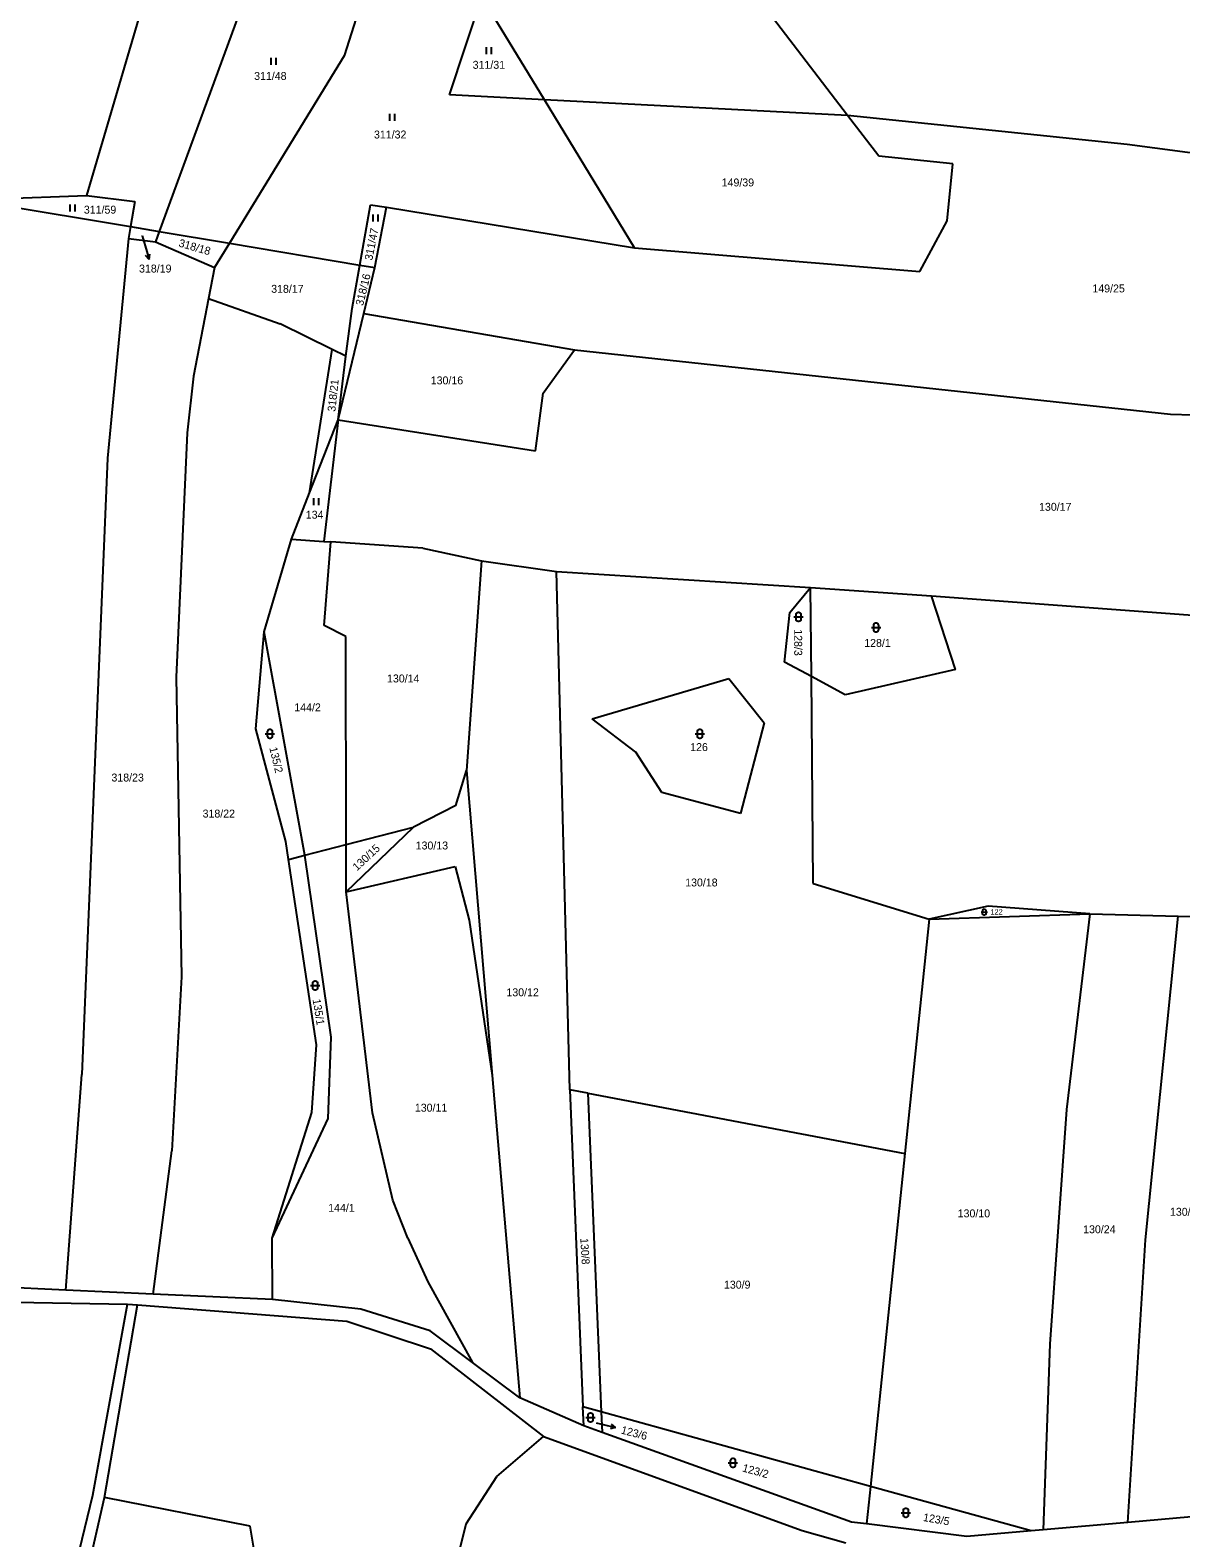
# Model space of a CAD drawing. Extents: x -791032 to -787751, y -1106872 to -1104403.
# Drawn here: x -789932.2 to -789685.4, y -1105545 to -1105221.6 of the extents above; entities that cross this region are included whole.
import ezdxf

# ---------------------------------------------------------------- set-up
doc = ezdxf.new("R2010")
doc.units = 0
for name, color, linetype in [('Komunikace', 7, 'Continuous'), ('Vrstva 1', 7, 'Continuous'), ('Vrstva 14', 7, 'Continuous'), ('Vrstva 16', 7, 'Continuous'), ('Vrstva 23', 7, 'Continuous')]:
    doc.layers.add(name, color=color, linetype=linetype)

msp = doc.modelspace()

# ---------------------------------------------------------------- linework, layer by layer
at = {"layer": 'Komunikace'}
for p, q in [((-789908.19, -1105265.74), (-789907.55, -1105267.91)), ((-789810.78, -1105520.32), (-789809.56, -1105520.63))]:
    msp.add_line(p, q, dxfattribs=at)
at = {"layer": 'Vrstva 1'}
for p, q in [((-789898.9, -1105184.93), (-789920.1, -1105257.09)), ((-789876.8, -1105189.18), (-789904.53, -1105264.78)), ((-789854.85, -1105195.52), (-789864.85, -1105227.14)), ((-789756.88, -1105239.91), (-789778.37, -1105211.87)), ((-789842.27, -1105235.52), (-789835.33, -1105214.49)), ((-789821.88, -1105236.57), (-789835.33, -1105214.49)), ((-789864.85, -1105227.14), (-789889.45, -1105267.31)), ((-789821.88, -1105236.57), (-789842.27, -1105235.52)), ((-789756.88, -1105239.91), (-789821.88, -1105236.57)), ((-789802.56, -1105268.3), (-789821.88, -1105236.57)), ((-789696.9, -1105246.15), (-789756.88, -1105239.91)), ((-789750.21, -1105248.61), (-789756.88, -1105239.91)), ((-789618.05, -1105256.49), (-789696.9, -1105246.15)), ((-789734.32, -1105250.31), (-789750.21, -1105248.61)), ((-789735.55, -1105262.51), (-789734.32, -1105250.31)), ((-789945.15, -1105257.97), (-789920.1, -1105257.09)), ((-789945.15, -1105257.97), (-789910.66, -1105263.75)), ((-789920.1, -1105257.09), (-789909.78, -1105258.37)), ((-789909.78, -1105258.37), (-789910.66, -1105263.75)), ((-789861.5, -1105272), (-789859.18, -1105259.05)), ((-789859.18, -1105259.05), (-789855.77, -1105259.61)), ((-789858.3, -1105272.54), (-789855.77, -1105259.61)), ((-789855.77, -1105259.61), (-789802.56, -1105268.3)), ((-789741.41, -1105273.39), (-789735.55, -1105262.51)), ((-789910.66, -1105263.75), (-789911.08, -1105266.33)), ((-789910.66, -1105263.75), (-789904.53, -1105264.78)), ((-789904.53, -1105264.78), (-789905.34, -1105267)), ((-789904.53, -1105264.78), (-789889.45, -1105267.31)), ((-789911.08, -1105266.33), (-789915.61, -1105313.42)), ((-789911.08, -1105266.33), (-789905.34, -1105267)), ((-789905.34, -1105267), (-789892.65, -1105272.54)), ((-789889.45, -1105267.31), (-789892.65, -1105272.54)), ((-789889.45, -1105267.31), (-789861.5, -1105272)), ((-789802.56, -1105268.3), (-789741.41, -1105273.39)), ((-789863.17, -1105281.31), (-789861.5, -1105272)), ((-789861.5, -1105272), (-789858.3, -1105272.54)), ((-789892.65, -1105272.54), (-789893.94, -1105279.16)), ((-789860.67, -1105282.39), (-789858.3, -1105272.54)), ((-789893.94, -1105279.16), (-789897.2, -1105295.83)), ((-789893.94, -1105279.16), (-789878.56, -1105284.6)), ((-789864.46, -1105291.57), (-789863.17, -1105281.31)), ((-789867.4, -1105290.11), (-789878.56, -1105284.6)), ((-789866.17, -1105305.19), (-789860.67, -1105282.39)), ((-789860.67, -1105282.39), (-789815.45, -1105290.19)), ((-789872.27, -1105320.87), (-789867.4, -1105290.11)), ((-789864.46, -1105291.57), (-789867.4, -1105290.11)), ((-789866.17, -1105305.19), (-789864.46, -1105291.57)), ((-789822.2, -1105299.47), (-789815.45, -1105290.19)), ((-789815.45, -1105290.19), (-789687.61, -1105303.97)), ((-789897.2, -1105295.83), (-789898.51, -1105308.02)), ((-789823.79, -1105311.85), (-789822.2, -1105299.47)), ((-789687.61, -1105303.97), (-789663.28, -1105304.71)), ((-789898.51, -1105308.02), (-789900.89, -1105360.37)), ((-789872.27, -1105320.87), (-789866.17, -1105305.19)), ((-789866.17, -1105305.19), (-789869.21, -1105331.3)), ((-789866.17, -1105305.19), (-789823.79, -1105311.85)), ((-789915.61, -1105313.42), (-789921.14, -1105445.65)), ((-789876.15, -1105330.83), (-789872.27, -1105320.87)), ((-789882.03, -1105350.67), (-789876.15, -1105330.83)), ((-789876.15, -1105330.83), (-789869.21, -1105331.3)), ((-789869.21, -1105331.3), (-789867.7, -1105331.4)), ((-789869.11, -1105349.31), (-789867.7, -1105331.4)), ((-789848, -1105332.7), (-789867.7, -1105331.4)), ((-789848, -1105332.7), (-789835.42, -1105335.45)), ((-789835.42, -1105335.45), (-789838.65, -1105380.44)), ((-789835.42, -1105335.45), (-789819.35, -1105337.71)), ((-789819.35, -1105337.71), (-789764.83, -1105341.18)), ((-789816.49, -1105448.92), (-789819.35, -1105337.71)), ((-789769.27, -1105346.53), (-789764.83, -1105341.18)), ((-789764.83, -1105341.18), (-789738.92, -1105342.96)), ((-789764.66, -1105360.28), (-789764.83, -1105341.18)), ((-789733.72, -1105358.79), (-789738.92, -1105342.96)), ((-789738.92, -1105342.96), (-789559.95, -1105356.13)), ((-789770.44, -1105357.17), (-789769.27, -1105346.53)), ((-789864.52, -1105351.67), (-789869.11, -1105349.31)), ((-789883.79, -1105371.5), (-789882.03, -1105350.67)), ((-789873.29, -1105398.59), (-789882.03, -1105350.67)), ((-789864.42, -1105396.31), (-789864.52, -1105351.67)), ((-789764.66, -1105360.28), (-789770.44, -1105357.17)), ((-789733.72, -1105358.79), (-789757.4, -1105364.19)), ((-789900.89, -1105360.37), (-789899.74, -1105424.65)), ((-789811.7, -1105369.36), (-789782.32, -1105360.67)), ((-789782.32, -1105360.67), (-789774.8, -1105370.19)), ((-789757.4, -1105364.19), (-789764.66, -1105360.28)), ((-789764.25, -1105404.69), (-789764.66, -1105360.28)), ((-789802.29, -1105376.51), (-789811.7, -1105369.36)), ((-789877.39, -1105395.62), (-789883.79, -1105371.5)), ((-789774.8, -1105370.19), (-789779.84, -1105389.62)), ((-789796.71, -1105385.15), (-789802.29, -1105376.51)), ((-789840.88, -1105387.94), (-789838.65, -1105380.44)), ((-789838.65, -1105380.44), (-789833.09, -1105445.85)), ((-789779.84, -1105389.62), (-789796.71, -1105385.15)), ((-789840.88, -1105387.94), (-789850, -1105392.59)), ((-789864.42, -1105396.31), (-789850, -1105392.59)), ((-789864.4, -1105406.48), (-789850, -1105392.59)), ((-789876.81, -1105399.51), (-789877.39, -1105395.62)), ((-789876.81, -1105399.51), (-789873.29, -1105398.59)), ((-789873.29, -1105398.59), (-789864.42, -1105396.31)), ((-789867.63, -1105437.61), (-789873.29, -1105398.59)), ((-789864.4, -1105406.48), (-789864.42, -1105396.31)), ((-789870.82, -1105439.27), (-789876.81, -1105399.51)), ((-789864.4, -1105406.48), (-789841.03, -1105400.98)), ((-789841.03, -1105400.98), (-789838.03, -1105412.49)), ((-789764.25, -1105404.69), (-789739.37, -1105412.28)), ((-789858.75, -1105453.85), (-789864.4, -1105406.48)), ((-789726.73, -1105409.55), (-789739.37, -1105412.28)), ((-789739.37, -1105412.28), (-789704.93, -1105411.19)), ((-789704.93, -1105411.19), (-789726.73, -1105409.55)), ((-789704.93, -1105411.19), (-789709.91, -1105453.12)), ((-789704.93, -1105411.19), (-789686.01, -1105411.64)), ((-789838.03, -1105412.49), (-789833.09, -1105445.85)), ((-789739.37, -1105412.28), (-789744.59, -1105462.54)), ((-789693.02, -1105481.06), (-789686.01, -1105411.64)), ((-789686.01, -1105411.64), (-789667.88, -1105412.07)), ((-789899.74, -1105424.65), (-789901.79, -1105461.99)), ((-789871.82, -1105453.76), (-789870.82, -1105439.27)), ((-789868.28, -1105455.1), (-789867.63, -1105437.61)), ((-789924.58, -1105491.88), (-789921.14, -1105445.65)), ((-789833.09, -1105445.85), (-789827.21, -1105515)), ((-789812.58, -1105449.66), (-789816.49, -1105448.92)), ((-789816.49, -1105448.92), (-789813.64, -1105516.91)), ((-789812.58, -1105449.66), (-789744.59, -1105462.54)), ((-789812.58, -1105449.66), (-789809.7, -1105518)), ((-789709.91, -1105453.12), (-789713.54, -1105503.51)), ((-789880.28, -1105480.76), (-789871.82, -1105453.76)), ((-789880.28, -1105480.76), (-789868.28, -1105455.1)), ((-789854.4, -1105472.57), (-789858.75, -1105453.85)), ((-789905.81, -1105492.73), (-789901.79, -1105461.99)), ((-789744.59, -1105462.54), (-789752, -1105533.98)), ((-789851.22, -1105480.73), (-789854.4, -1105472.57)), ((-789880.25, -1105493.9), (-789880.28, -1105480.76)), ((-789851.22, -1105480.73), (-789846.93, -1105490.11)), ((-789696.75, -1105541.71), (-789693.02, -1105481.06)), ((-789924.58, -1105491.88), (-789962.46, -1105490.15)), ((-789905.81, -1105492.73), (-789924.58, -1105491.88)), ((-789846.93, -1105490.11), (-789837.3, -1105507.43)), ((-789968.63, -1105493.94), (-789911.33, -1105494.89)), ((-789918.75, -1105535.87), (-789911.33, -1105494.89)), ((-789916.23, -1105536.35), (-789909.16, -1105495.06)), ((-789911.33, -1105494.89), (-789909.16, -1105495.06)), ((-789909.16, -1105495.06), (-789864.3, -1105498.57)), ((-789880.25, -1105493.9), (-789905.81, -1105492.73)), ((-789861.27, -1105495.99), (-789880.25, -1105493.9)), ((-789864.3, -1105498.57), (-789846.35, -1105504.45)), ((-789846.42, -1105500.6), (-789861.27, -1105495.99)), ((-789837.3, -1105507.43), (-789846.42, -1105500.6)), ((-789846.35, -1105504.45), (-789822.11, -1105523.27)), ((-789713.54, -1105503.51), (-789714.97, -1105543.3)), ((-789827.21, -1105515), (-789837.3, -1105507.43)), ((-789813.47, -1105520.96), (-789827.21, -1105515)), ((-789809.7, -1105518), (-789813.64, -1105516.91)), ((-789813.47, -1105520.96), (-789813.64, -1105516.91)), ((-789752, -1105533.98), (-789809.7, -1105518)), ((-789809.7, -1105518), (-789809.51, -1105522.39)), ((-789809.51, -1105522.39), (-789813.47, -1105520.96)), ((-789832.11, -1105531.85), (-789822.11, -1105523.27)), ((-789822.11, -1105523.27), (-789766.64, -1105543.45)), ((-789756.02, -1105541.64), (-789809.51, -1105522.39)), ((-789838.71, -1105542.04), (-789832.11, -1105531.85)), ((-789752, -1105533.98), (-789752.84, -1105542.04)), ((-789717.55, -1105543.53), (-789752, -1105533.98)), ((-789930, -1105581.73), (-789918.75, -1105535.87)), ((-789926.61, -1105581.71), (-789916.23, -1105536.35)), ((-789884.98, -1105542.5), (-789916.23, -1105536.35)), ((-789679.89, -1105540.23), (-789696.75, -1105541.71)), ((-789882.2, -1105559.31), (-789884.98, -1105542.5)), ((-789841.82, -1105554.77), (-789838.71, -1105542.04)), ((-789766.64, -1105543.45), (-789757.27, -1105546.07)), ((-789752.84, -1105542.04), (-789756.02, -1105541.64)), ((-789731.29, -1105544.73), (-789752.84, -1105542.04)), ((-789717.55, -1105543.53), (-789731.29, -1105544.73)), ((-789714.97, -1105543.3), (-789717.55, -1105543.53)), ((-789696.75, -1105541.71), (-789714.97, -1105543.3))]:
    msp.add_line(p, q, dxfattribs=at)
at = {"layer": 'Vrstva 16'}
for p, q in [((-789907.55, -1105267.91), (-789906.701, -1105270.787)), ((-789906.701, -1105270.787), (-789907.463, -1105269.969)), ((-789906.701, -1105270.787), (-789906.504, -1105269.686)), ((-789809.56, -1105520.63), (-789806.65, -1105521.362)), ((-789806.65, -1105521.362), (-789807.742, -1105521.603)), ((-789806.65, -1105521.362), (-789807.498, -1105520.633))]:
    msp.add_line(p, q, dxfattribs=at)
at = {"layer": 'Vrstva 23'}
for p, q in [((-789834.31, -1105226.78), (-789834.31, -1105225.28)), ((-789833.31, -1105225.28), (-789833.31, -1105226.78)), ((-789880.54, -1105229.04), (-789880.54, -1105227.54)), ((-789879.54, -1105227.54), (-789879.54, -1105229.04)), ((-789855.07, -1105241.07), (-789855.07, -1105239.57)), ((-789854.07, -1105239.57), (-789854.07, -1105241.07)), ((-789923.61, -1105260.51), (-789923.61, -1105259.01)), ((-789922.61, -1105259.01), (-789922.61, -1105260.51)), ((-789858.62, -1105262.63), (-789858.62, -1105261.13)), ((-789857.62, -1105261.13), (-789857.62, -1105262.63)), ((-789871.34, -1105323.5), (-789871.34, -1105322)), ((-789870.34, -1105322), (-789870.34, -1105323.5)), ((-789767.91, -1105346.89), (-789767.81, -1105346.69)), ((-789767.81, -1105346.69), (-789767.71, -1105346.59)), ((-789767.71, -1105346.59), (-789767.51, -1105346.49)), ((-789767.51, -1105346.49), (-789767.31, -1105346.49)), ((-789767.31, -1105346.49), (-789767.11, -1105346.59)), ((-789767.11, -1105346.59), (-789767.01, -1105346.69)), ((-789767.01, -1105346.69), (-789766.91, -1105346.89)), ((-789768.41, -1105347.49), (-789766.41, -1105347.49)), ((-789767.91, -1105348.09), (-789767.91, -1105346.89)), ((-789767.81, -1105348.29), (-789767.91, -1105348.09)), ((-789767.71, -1105348.39), (-789767.81, -1105348.29)), ((-789767.51, -1105348.49), (-789767.71, -1105348.39)), ((-789767.31, -1105348.49), (-789767.51, -1105348.49)), ((-789767.11, -1105348.39), (-789767.31, -1105348.49)), ((-789767.01, -1105348.29), (-789767.11, -1105348.39)), ((-789766.91, -1105348.09), (-789767.01, -1105348.29)), ((-789766.91, -1105346.89), (-789766.91, -1105348.09)), ((-789751.78, -1105349.75), (-789749.78, -1105349.75)), ((-789751.28, -1105349.15), (-789751.18, -1105348.95)), ((-789751.28, -1105350.35), (-789751.28, -1105349.15)), ((-789751.18, -1105348.95), (-789751.08, -1105348.85)), ((-789751.08, -1105348.85), (-789750.88, -1105348.75)), ((-789750.88, -1105348.75), (-789750.68, -1105348.75)), ((-789750.68, -1105348.75), (-789750.48, -1105348.85)), ((-789750.48, -1105348.85), (-789750.38, -1105348.95)), ((-789750.38, -1105348.95), (-789750.28, -1105349.15)), ((-789750.28, -1105349.15), (-789750.28, -1105350.35)), ((-789751.18, -1105350.55), (-789751.28, -1105350.35)), ((-789751.08, -1105350.65), (-789751.18, -1105350.55)), ((-789750.88, -1105350.75), (-789751.08, -1105350.65)), ((-789750.68, -1105350.75), (-789750.88, -1105350.75)), ((-789750.48, -1105350.65), (-789750.68, -1105350.75)), ((-789750.38, -1105350.55), (-789750.48, -1105350.65)), ((-789750.28, -1105350.35), (-789750.38, -1105350.55)), ((-789881.78, -1105372.56), (-789879.78, -1105372.56)), ((-789881.28, -1105371.96), (-789881.18, -1105371.76)), ((-789881.28, -1105373.16), (-789881.28, -1105371.96)), ((-789881.18, -1105371.76), (-789881.08, -1105371.66)), ((-789881.08, -1105371.66), (-789880.88, -1105371.56)), ((-789880.88, -1105371.56), (-789880.68, -1105371.56)), ((-789880.68, -1105371.56), (-789880.48, -1105371.66)), ((-789880.48, -1105371.66), (-789880.38, -1105371.76)), ((-789880.38, -1105371.76), (-789880.28, -1105371.96)), ((-789880.28, -1105371.96), (-789880.28, -1105373.16)), ((-789789.58, -1105372.55), (-789787.58, -1105372.55)), ((-789789.08, -1105371.95), (-789788.98, -1105371.75)), ((-789789.08, -1105373.15), (-789789.08, -1105371.95)), ((-789788.98, -1105371.75), (-789788.88, -1105371.65)), ((-789788.88, -1105371.65), (-789788.68, -1105371.55)), ((-789788.68, -1105371.55), (-789788.48, -1105371.55)), ((-789788.48, -1105371.55), (-789788.28, -1105371.65)), ((-789788.28, -1105371.65), (-789788.18, -1105371.75)), ((-789788.18, -1105371.75), (-789788.08, -1105371.95)), ((-789788.08, -1105371.95), (-789788.08, -1105373.15)), ((-789881.18, -1105373.36), (-789881.28, -1105373.16)), ((-789881.08, -1105373.46), (-789881.18, -1105373.36)), ((-789880.88, -1105373.56), (-789881.08, -1105373.46)), ((-789880.68, -1105373.56), (-789880.88, -1105373.56)), ((-789880.48, -1105373.46), (-789880.68, -1105373.56)), ((-789880.38, -1105373.36), (-789880.48, -1105373.46)), ((-789880.28, -1105373.16), (-789880.38, -1105373.36)), ((-789788.98, -1105373.35), (-789789.08, -1105373.15)), ((-789788.88, -1105373.45), (-789788.98, -1105373.35)), ((-789788.68, -1105373.55), (-789788.88, -1105373.45)), ((-789788.48, -1105373.55), (-789788.68, -1105373.55)), ((-789788.28, -1105373.45), (-789788.48, -1105373.55)), ((-789788.18, -1105373.35), (-789788.28, -1105373.45)), ((-789788.08, -1105373.15), (-789788.18, -1105373.35)), ((-789728.25, -1105410.762), (-789726.912, -1105410.839)), ((-789727.939, -1105411.183), (-789727.892, -1105410.38)), ((-789727.879, -1105411.32), (-789727.939, -1105411.183)), ((-789727.892, -1105410.38), (-789727.818, -1105410.25)), ((-789727.816, -1105411.391), (-789727.879, -1105411.32)), ((-789727.818, -1105410.25), (-789727.747, -1105410.187)), ((-789727.686, -1105411.466), (-789727.816, -1105411.391)), ((-789727.747, -1105410.187), (-789727.609, -1105410.128)), ((-789727.553, -1105411.473), (-789727.686, -1105411.466)), ((-789727.609, -1105410.128), (-789727.475, -1105410.136)), ((-789727.415, -1105411.414), (-789727.553, -1105411.473)), ((-789727.475, -1105410.136), (-789727.346, -1105410.21)), ((-789727.344, -1105411.351), (-789727.415, -1105411.414)), ((-789727.346, -1105410.21), (-789727.282, -1105410.281)), ((-789727.27, -1105411.221), (-789727.344, -1105411.351)), ((-789727.282, -1105410.281), (-789727.223, -1105410.419)), ((-789727.223, -1105410.419), (-789727.27, -1105411.221)), ((-789872.07, -1105426.56), (-789870.07, -1105426.56)), ((-789871.57, -1105425.96), (-789871.47, -1105425.76)), ((-789871.57, -1105427.16), (-789871.57, -1105425.96)), ((-789871.47, -1105427.36), (-789871.57, -1105427.16)), ((-789871.47, -1105425.76), (-789871.37, -1105425.66)), ((-789871.37, -1105427.46), (-789871.47, -1105427.36)), ((-789871.37, -1105425.66), (-789871.17, -1105425.56)), ((-789871.17, -1105427.56), (-789871.37, -1105427.46)), ((-789871.17, -1105425.56), (-789870.97, -1105425.56)), ((-789870.97, -1105427.56), (-789871.17, -1105427.56)), ((-789870.97, -1105425.56), (-789870.77, -1105425.66)), ((-789870.77, -1105427.46), (-789870.97, -1105427.56)), ((-789870.77, -1105425.66), (-789870.67, -1105425.76)), ((-789870.67, -1105427.36), (-789870.77, -1105427.46)), ((-789870.67, -1105425.76), (-789870.57, -1105425.96)), ((-789870.57, -1105427.16), (-789870.67, -1105427.36)), ((-789870.57, -1105425.96), (-789870.57, -1105427.16)), ((-789812.32, -1105518.3), (-789812.12, -1105518.2)), ((-789812.12, -1105518.2), (-789811.92, -1105518.2)), ((-789811.92, -1105518.2), (-789811.72, -1105518.3)), ((-789813.02, -1105519.2), (-789811.02, -1105519.2)), ((-789812.52, -1105518.6), (-789812.42, -1105518.4)), ((-789812.52, -1105519.8), (-789812.52, -1105518.6)), ((-789812.42, -1105520), (-789812.52, -1105519.8)), ((-789812.42, -1105518.4), (-789812.32, -1105518.3)), ((-789812.32, -1105520.1), (-789812.42, -1105520)), ((-789812.12, -1105520.2), (-789812.32, -1105520.1)), ((-789811.92, -1105520.2), (-789812.12, -1105520.2)), ((-789811.72, -1105520.1), (-789811.92, -1105520.2)), ((-789811.72, -1105518.3), (-789811.62, -1105518.4)), ((-789811.62, -1105520), (-789811.72, -1105520.1)), ((-789811.62, -1105518.4), (-789811.52, -1105518.6)), ((-789811.52, -1105519.8), (-789811.62, -1105520)), ((-789811.52, -1105518.6), (-789811.52, -1105519.8)), ((-789781.77, -1105528.04), (-789781.57, -1105527.94)), ((-789781.57, -1105527.94), (-789781.37, -1105527.94)), ((-789781.37, -1105527.94), (-789781.17, -1105528.04)), ((-789782.47, -1105528.94), (-789780.47, -1105528.94)), ((-789781.97, -1105528.34), (-789781.87, -1105528.14)), ((-789781.97, -1105529.54), (-789781.97, -1105528.34)), ((-789781.87, -1105529.74), (-789781.97, -1105529.54)), ((-789781.87, -1105528.14), (-789781.77, -1105528.04)), ((-789781.77, -1105529.84), (-789781.87, -1105529.74)), ((-789781.57, -1105529.94), (-789781.77, -1105529.84)), ((-789781.37, -1105529.94), (-789781.57, -1105529.94)), ((-789781.17, -1105529.84), (-789781.37, -1105529.94)), ((-789781.17, -1105528.04), (-789781.07, -1105528.14)), ((-789781.07, -1105529.74), (-789781.17, -1105529.84)), ((-789781.07, -1105528.14), (-789780.97, -1105528.34)), ((-789780.97, -1105529.54), (-789781.07, -1105529.74)), ((-789780.97, -1105528.34), (-789780.97, -1105529.54)), ((-789745.39, -1105539.63), (-789743.39, -1105539.63)), ((-789744.89, -1105539.03), (-789744.79, -1105538.83)), ((-789744.89, -1105540.23), (-789744.89, -1105539.03)), ((-789744.79, -1105540.43), (-789744.89, -1105540.23)), ((-789744.79, -1105538.83), (-789744.69, -1105538.73)), ((-789744.69, -1105540.53), (-789744.79, -1105540.43)), ((-789744.69, -1105538.73), (-789744.49, -1105538.63)), ((-789744.49, -1105540.63), (-789744.69, -1105540.53)), ((-789744.49, -1105538.63), (-789744.29, -1105538.63)), ((-789744.29, -1105540.63), (-789744.49, -1105540.63)), ((-789744.29, -1105538.63), (-789744.09, -1105538.73)), ((-789744.09, -1105540.53), (-789744.29, -1105540.63)), ((-789744.09, -1105538.73), (-789743.99, -1105538.83)), ((-789743.99, -1105540.43), (-789744.09, -1105540.53)), ((-789743.99, -1105538.83), (-789743.89, -1105539.03)), ((-789743.89, -1105540.23), (-789743.99, -1105540.43)), ((-789743.89, -1105539.03), (-789743.89, -1105540.23))]:
    msp.add_line(p, q, dxfattribs=at)

# ---------------------------------------------------------------- texts
at = {"layer": 'Vrstva 14'}
for s, height, p in [('311/31', 1.7, (-789837.29, -1105229.9)), ('311/48', 1.7, (-789884.162, -1105232.29)), ('311/32', 1.7, (-789858.456, -1105244.85)), ('149/39', 1.7, (-789783.889, -1105255.13)), ('311/59', 1.7, (-789920.683, -1105260.97)), ('318/19', 0.1, (-789908.412, -1105265.74)), ('318/17', 1.7, (-789880.503, -1105277.95)), ('149/25', 1.7, (-789704.385, -1105277.87)), ('130/16', 1.7, (-789846.286, -1105297.59)), ('130/17', 1.7, (-789715.822, -1105324.71)), ('134', 1.7, (-789873.086, -1105326.4)), ('128/1', 1.7, (-789753.316, -1105353.91)), ('130/14', 1.7, (-789855.661, -1105361.53)), ('144/2', 1.7, (-789875.545, -1105367.73)), ('126', 1.7, (-789790.65, -1105376.25)), ('318/23', 1.7, (-789914.763, -1105382.78)), ('318/22', 1.7, (-789895.213, -1105390.51)), ('130/13', 1.7, (-789849.516, -1105397.36)), ('130/18', 1.7, (-789791.715, -1105405.29)), ('122', 1.14, (-789726.247, -1105411.32)), ('130/12', 1.7, (-789830.055, -1105428.85)), ('130/11', 1.7, (-789849.689, -1105453.6)), ('144/1', 1.7, (-789868.278, -1105475.08)), ('130/10', 1.7, (-789733.275, -1105476.27)), ('130/25', 1.7, (-789687.748, -1105475.93)), ('130/24', 1.7, (-789706.368, -1105479.68)), ('130/9', 1.7, (-789783.402, -1105491.56)), ('123/6', 0.1, (-789810.971, -1105520.32))]:
    msp.add_text(s, height=height, dxfattribs=at).set_placement(p)
for s, rotation, p in [('311/47', 78.93792, (-789858.83, -1105271.098)), ('318/18', 343.95399, (-789900.48, -1105267.991)), ('318/16', 76.28409, (-789860.805, -1105280.838)), ('318/21', 83.91762, (-789866.748, -1105303.515)), ('128/3', 270, (-789768.33, -1105350.126)), ('135/2', 283.53114, (-789880.917, -1105375.591)), ('130/15', 43.02504, (-789862.089, -1105402.064)), ('135/1', 279.30717, (-789871.633, -1105429.546)), ('130/8', 273.40641, (-789814.213, -1105480.763)), ('123/2', 344.62197, (-789779.587, -1105530.749)), ('123/5', 350.08425, (-789740.79, -1105541.385))]:
    msp.add_text(s, height=1.7, rotation=rotation, dxfattribs=at).set_placement(p)
at = {"layer": 'Vrstva 16'}
msp.add_text('318/19', height=1.7, dxfattribs=at).set_placement((-789908.84, -1105273.6))
msp.add_text('123/6', height=1.7, rotation=345.17817, dxfattribs=at).set_placement((-789805.614, -1105522.613))

doc.saveas('drawing.dxf')
